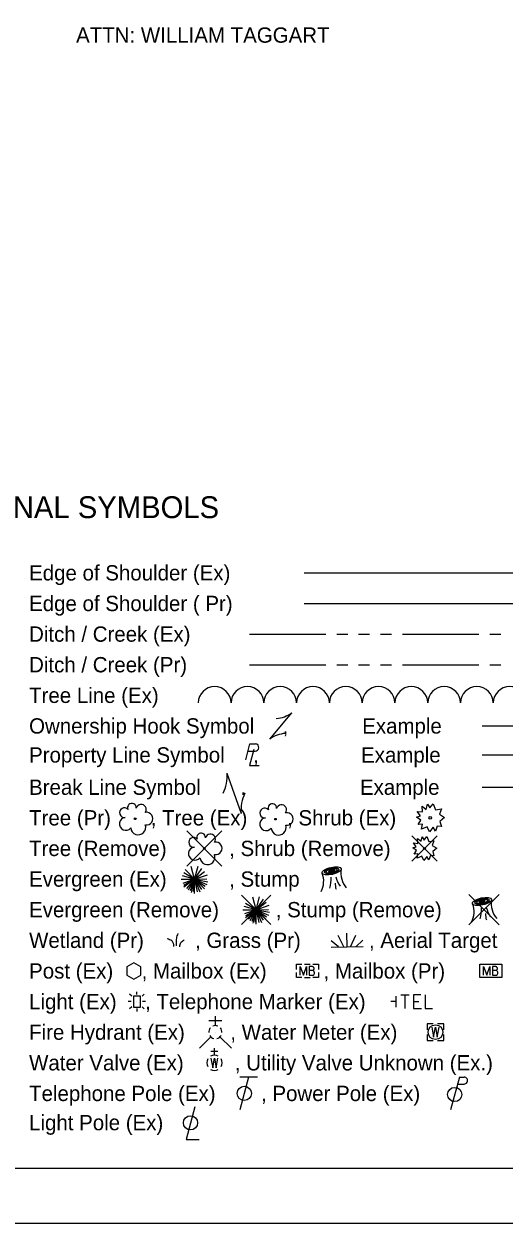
# Model space of a CAD drawing. Extents: x 0 to 34, y 0 to 22.
# Drawn here: x 8.12 to 12.52, y 0 to 10.96 of the extents above; entities that cross this region are included whole.
import ezdxf

# ---------------------------------------------------------------- set-up
doc = ezdxf.new("R2010")
doc.units = 0
for name, color, linetype in [('SH_Border', 7, 'Continuous'), ('SH_Cut_Line', 7, 'Continuous'), ('SH_Text', 7, 'Continuous')]:
    doc.layers.add(name, color=color, linetype=linetype)

msp = doc.modelspace()

# ---------------------------------------------------------------- linework, layer by layer
at = {"layer": 'SH_Border'}
msp.add_lwpolyline([(1.5, 21.5), (33.5, 21.5), (33.5, 0.5), (1.5, 0.5)], close=True, dxfattribs=at)
at = {"layer": 'SH_Cut_Line'}
msp.add_lwpolyline([(0, 0), (34, 0), (34, 22), (0, 22)], close=True, dxfattribs=at)
at = {"layer": 'SH_Text'}
for p, q in [((10.688, 5.945), (14.172, 5.945)), ((10.688, 5.665), (14.172, 5.665)), ((10.188, 5.385), (10.888, 5.385)), ((10.988, 5.385), (11.088, 5.385)), ((11.188, 5.385), (11.288, 5.385)), ((11.388, 5.385), (11.488, 5.385)), ((11.588, 5.385), (12.288, 5.385)), ((12.388, 5.385), (12.488, 5.385)), ((10.188, 5.105), (10.888, 5.105)), ((10.988, 5.105), (11.088, 5.105)), ((11.188, 5.105), (11.288, 5.105)), ((11.388, 5.105), (11.488, 5.105)), ((11.588, 5.105), (12.288, 5.105)), ((12.388, 5.105), (12.488, 5.105)), ((10.375, 4.425), (10.575, 4.665)), ((10.475, 4.545), (10.475, 4.545)), ((12.318, 4.545), (14.1, 4.545)), ((10.175, 4.314), (10.24, 4.314)), ((10.215, 4.283), (10.215, 4.283)), ((12.318, 4.28), (14.1, 4.28)), ((9.983, 4.113), (10.113, 3.745)), ((12.318, 3.985), (13.083, 3.985)), ((10.048, 3.929), (10.048, 3.929)), ((9.616, 3.585), (9.936, 3.264)), ((9.936, 3.585), (9.616, 3.264)), ((11.675, 3.541), (11.906, 3.309)), ((11.906, 3.541), (11.675, 3.309)), ((9.776, 3.425), (9.776, 3.425)), ((11.791, 3.425), (11.791, 3.425)), ((9.686, 3.144), (9.589, 3.202)), ((9.686, 3.144), (9.599, 3.232)), ((9.686, 3.144), (9.656, 3.26)), ((9.686, 3.144), (9.718, 3.262)), ((9.686, 3.144), (9.753, 3.242)), ((9.686, 3.144), (9.778, 3.215)), ((9.686, 3.144), (9.805, 3.185)), ((9.563, 3.144), (9.686, 3.144)), ((9.686, 3.144), (9.576, 3.174)), ((9.686, 3.144), (9.579, 3.105)), ((9.686, 3.144), (9.587, 3.087)), ((9.686, 3.144), (9.589, 3.07)), ((9.686, 3.144), (9.613, 3.058)), ((9.686, 3.144), (9.628, 3.044)), ((9.686, 3.144), (9.645, 3.036)), ((9.686, 3.144), (9.655, 3.023)), ((9.686, 3.144), (9.673, 3.03)), ((9.686, 3.144), (9.799, 3.147)), ((9.686, 3.013), (9.686, 3.144)), ((9.686, 3.144), (9.709, 3.029)), ((9.686, 3.144), (9.735, 3.028)), ((9.686, 3.144), (9.75, 3.05)), ((9.686, 3.144), (9.776, 3.056)), ((9.686, 3.144), (9.782, 3.081)), ((9.686, 3.144), (9.798, 3.096)), ((9.686, 3.144), (9.807, 3.12)), ((10.96, 3.145), (10.96, 3.145)), ((10.117, 2.998), (10.384, 2.731)), ((10.384, 2.998), (10.117, 2.731)), ((10.25, 2.865), (10.22, 2.98)), ((10.25, 2.865), (10.282, 2.982)), ((10.25, 2.865), (10.317, 2.962)), ((12.197, 3.004), (12.475, 2.726)), ((12.475, 3.004), (12.197, 2.726)), ((10.127, 2.865), (10.25, 2.865)), ((10.25, 2.865), (10.14, 2.894)), ((10.25, 2.865), (10.143, 2.826)), ((10.25, 2.865), (10.151, 2.808)), ((10.25, 2.865), (10.153, 2.922)), ((10.25, 2.865), (10.153, 2.79)), ((10.25, 2.865), (10.163, 2.952)), ((10.25, 2.865), (10.177, 2.778)), ((10.25, 2.865), (10.192, 2.764)), ((10.25, 2.865), (10.209, 2.756)), ((10.25, 2.865), (10.219, 2.743)), ((10.25, 2.865), (10.237, 2.75)), ((10.25, 2.865), (10.342, 2.935)), ((10.25, 2.865), (10.369, 2.905)), ((10.25, 2.865), (10.363, 2.867)), ((10.25, 2.734), (10.25, 2.865)), ((10.25, 2.865), (10.273, 2.749)), ((10.25, 2.865), (10.299, 2.748)), ((10.25, 2.865), (10.314, 2.77)), ((10.25, 2.865), (10.34, 2.777)), ((10.25, 2.865), (10.346, 2.801)), ((10.25, 2.865), (10.362, 2.816)), ((10.25, 2.865), (10.371, 2.841)), ((10.25, 2.865), (10.25, 2.865)), ((12.336, 2.865), (12.336, 2.865)), ((12.336, 2.865), (12.336, 2.865)), ((11.082, 2.525), (11.08, 2.65)), ((11.112, 2.525), (11.161, 2.633)), ((11.003, 2.524), (10.935, 2.581)), ((10.936, 2.522), (11.228, 2.527)), ((11.052, 2.524), (11, 2.63)), ((11.161, 2.526), (11.227, 2.585)), ((10.693, 2.366), (10.743, 2.366)), ((10.719, 2.305), (10.719, 2.305)), ((12.397, 2.305), (12.397, 2.305)), ((10.693, 2.244), (10.743, 2.244)), ((9.111, 2.073), (9.092, 2.092)), ((9.159, 2.089), (9.159, 2.115)), ((9.226, 2.092), (9.207, 2.073)), ((9.107, 2.025), (9.08, 2.025)), ((9.111, 1.976), (9.092, 1.958)), ((9.159, 2.025), (9.159, 2.025)), ((9.226, 1.958), (9.207, 1.976)), ((9.238, 2.025), (9.211, 2.025)), ((11.532, 2.025), (11.482, 2.025)), ((11.532, 1.975), (11.532, 2.075)), ((9.159, 1.961), (9.159, 1.934)), ((9.877, 1.805), (9.877, 1.891)), ((9.937, 1.848), (9.817, 1.848)), ((9.835, 1.702), (9.731, 1.598)), ((9.877, 1.745), (9.877, 1.745)), ((9.877, 1.745), (9.877, 1.745)), ((9.919, 1.702), (10.023, 1.598)), ((11.891, 1.745), (11.891, 1.745)), ((9.9, 1.567), (9.836, 1.567)), ((9.868, 1.535), (9.868, 1.598)), ((9.868, 1.465), (9.868, 1.465)), ((10.261, 1.335), (10.101, 1.335)), ((10.181, 1.335), (10.101, 1.035)), ((12.11, 1.335), (12.03, 1.035)), ((12.11, 1.335), (12.153, 1.335)), ((12.093, 1.271), (12.153, 1.271))]:
    msp.add_line(p, q, dxfattribs=at)
for points in [[(10.154, 4.234), (10.193, 4.382), (10.245, 4.382)], [(10.229, 4.331), (10.189, 4.183), (10.277, 4.183)], [(11.839, 3.795), (11.869, 3.832), (11.89, 3.779), (11.945, 3.788), (11.928, 3.738), (11.975, 3.708), (11.932, 3.671), (11.945, 3.626), (11.907, 3.629), (11.891, 3.583), (11.869, 3.618), (11.836, 3.577), (11.814, 3.621), (11.763, 3.6), (11.773, 3.647), (11.732, 3.643), (11.756, 3.682), (11.717, 3.711), (11.754, 3.724), (11.724, 3.764), (11.771, 3.759), (11.769, 3.81), (11.807, 3.782), (11.817, 3.831), (11.839, 3.795)], [(11.787, 3.502), (11.813, 3.533), (11.83, 3.488), (11.877, 3.496), (11.862, 3.453), (11.902, 3.427), (11.866, 3.396), (11.877, 3.357), (11.845, 3.36), (11.831, 3.321), (11.813, 3.351), (11.784, 3.316), (11.766, 3.354), (11.722, 3.336), (11.73, 3.376), (11.696, 3.372), (11.716, 3.406), (11.683, 3.43), (11.715, 3.441), (11.689, 3.475), (11.729, 3.47), (11.727, 3.515), (11.759, 3.49), (11.768, 3.532), (11.787, 3.502)], [(9.066, 2.267), (9.131, 2.23), (9.196, 2.267), (9.196, 2.342), (9.131, 2.38), (9.066, 2.342), (9.066, 2.267)], [(10.619, 2.317), (10.619, 2.366), (10.667, 2.366)], [(10.654, 2.265), (10.654, 2.345), (10.683, 2.265), (10.711, 2.345), (10.711, 2.265)], [(10.77, 2.308), (10.773, 2.311), (10.775, 2.313), (10.776, 2.315), (10.777, 2.316), (10.778, 2.319), (10.779, 2.321), (10.78, 2.325), (10.78, 2.327), (10.78, 2.33), (10.779, 2.333), (10.778, 2.336), (10.776, 2.339), (10.773, 2.342), (10.77, 2.343), (10.769, 2.343), (10.766, 2.345), (10.735, 2.345), (10.735, 2.265), (10.77, 2.265), (10.774, 2.267), (10.778, 2.27), (10.781, 2.275), (10.783, 2.281), (10.784, 2.287), (10.784, 2.291), (10.782, 2.294), (10.78, 2.3), (10.777, 2.304), (10.77, 2.308), (10.735, 2.308)], [(10.769, 2.366), (10.819, 2.366), (10.819, 2.317)], [(12.332, 2.265), (12.332, 2.345), (12.361, 2.265), (12.389, 2.345), (12.389, 2.265)], [(12.448, 2.308), (12.451, 2.311), (12.453, 2.313), (12.454, 2.315), (12.455, 2.316), (12.456, 2.319), (12.457, 2.321), (12.458, 2.325), (12.458, 2.327), (12.458, 2.33), (12.457, 2.333), (12.456, 2.336), (12.454, 2.339), (12.451, 2.342), (12.449, 2.343), (12.447, 2.343), (12.444, 2.345), (12.413, 2.345), (12.413, 2.265), (12.448, 2.265), (12.452, 2.267), (12.456, 2.27), (12.459, 2.275), (12.461, 2.281), (12.462, 2.287), (12.462, 2.291), (12.461, 2.294), (12.458, 2.3), (12.455, 2.304), (12.448, 2.308), (12.413, 2.308)], [(10.667, 2.244), (10.619, 2.244), (10.619, 2.292)], [(10.819, 2.292), (10.819, 2.244), (10.769, 2.244)], [(11.573, 2.087), (11.65, 2.087)], [(11.612, 2.087), (11.612, 1.962)], [(11.758, 2.087), (11.69, 2.087), (11.69, 1.962), (11.763, 1.962)], [(11.797, 2.087), (11.797, 1.962), (11.865, 1.962)], [(11.69, 2.025), (11.738, 2.025)], [(11.871, 1.82), (11.816, 1.82), (11.816, 1.765)], [(11.857, 1.79), (11.874, 1.7), (11.891, 1.79), (11.907, 1.7), (11.924, 1.79)], [(11.966, 1.765), (11.966, 1.82), (11.911, 1.82)], [(11.816, 1.725), (11.816, 1.67), (11.871, 1.67)], [(11.911, 1.67), (11.966, 1.67), (11.966, 1.725)], [(9.836, 1.506), (9.852, 1.42), (9.868, 1.506), (9.884, 1.42), (9.9, 1.506)], [(9.688, 1.063), (9.61, 0.764), (9.728, 0.764)]]:
    msp.add_lwpolyline(points, dxfattribs=at)
for points in [[(12.297, 2.366), (12.497, 2.366), (12.497, 2.244), (12.297, 2.244)], [(9.126, 1.975), (9.192, 1.975), (9.192, 2.075), (9.126, 2.075)]]:
    msp.add_lwpolyline(points, close=True, dxfattribs=at)
for centre, radius in [((9.143, 3.697), 0.0084), ((10.427, 3.693), 0.0072), ((11.843, 3.705), 0.0115), ((9.776, 3.425), 0.0072), ((11.79, 3.425), 0.00979), ((11.891, 1.745), 0.0675), ((10.141, 1.185), 0.065), ((12.067, 1.175), 0.065), ((9.649, 0.916), 0.065)]:
    msp.add_circle(centre, radius, dxfattribs=at)
for centre, radius, start, end in [((9.87, 4.755), 0.15, 0.0098, 179.9926), ((10.17, 4.755), 0.15, 0.0098, 179.9926), ((10.47, 4.755), 0.15, 0.0098, 179.9926), ((10.77, 4.755), 0.15, 0.0098, 179.9926), ((11.07, 4.755), 0.15, 0.0098, 179.9926), ((11.37, 4.755), 0.15, 0.0098, 179.9926), ((11.67, 4.755), 0.15, 0.0098, 179.9926), ((11.97, 4.755), 0.15, 0.0098, 179.9926), ((12.27, 4.755), 0.15, 0.0098, 179.9926), ((12.57, 4.755), 0.15, 0.0098, 179.9926), ((10.417, 4.88), 0.267, 273.6945, 306.337), ((10.533, 4.21), 0.267, 93.6945, 126.337), ((10.24, 4.348), 0.0345, 270.471, 81.3281), ((9.651, 4.081), 0.334, 332.9422, 5.5848), ((10.445, 3.777), 0.334, 152.9422, 185.5848), ((9.044, 3.752), 0.0441, 39.0625, 279.5412), ((9.113, 3.798), 0.0395, 354.0047, 205.9741), ((9.198, 3.781), 0.0466, 323.83, 165.0376), ((9.247, 3.698), 0.0574, 259.1453, 101.4596), ((10.328, 3.749), 0.0441, 39.0625, 279.5412), ((10.398, 3.794), 0.0395, 354.0047, 205.9741), ((10.482, 3.778), 0.0466, 323.83, 165.0376), ((10.531, 3.694), 0.0574, 259.1453, 101.4596), ((9.057, 3.65), 0.0592, 96.1722, 320.5737), ((9.171, 3.618), 0.0685, 184.9476, 19.4572), ((10.342, 3.647), 0.0592, 96.1722, 320.5737), ((10.456, 3.615), 0.0685, 184.9476, 19.4572), ((9.677, 3.481), 0.0441, 39.0625, 279.5412), ((9.746, 3.526), 0.0395, 354.0047, 205.9741), ((9.831, 3.51), 0.0466, 323.83, 165.0376), ((9.69, 3.378), 0.0592, 96.1722, 320.5737), ((9.88, 3.426), 0.0574, 259.1453, 101.4596), ((9.804, 3.346), 0.0685, 184.9476, 19.4572), ((10.668, 3.127), 0.2, 331.5338, 20.9269), ((11.24, 3.202), 0.215, 171.4106, 219.9194), ((10.684, 3.146), 0.253, 340.7938, 3.5481), ((11.155, 3.105), 0.182, 178.7926, 197.1224), ((11.285, 3.247), 0.316, 194.9653, 212.1216), ((12.044, 2.847), 0.2, 331.5338, 20.9269), ((12.06, 2.866), 0.253, 340.7938, 3.5481), ((12.661, 2.967), 0.316, 194.9653, 212.1216), ((12.616, 2.922), 0.215, 171.4106, 219.9194), ((12.531, 2.825), 0.182, 178.7926, 197.1224), ((9.877, 1.745), 0.06, 140.021, 184.0629), ((9.877, 1.745), 0.06, 68.1395, 112.038), ((9.877, 1.745), 0.06, 356.0165, 39.9889), ((9.877, 1.745), 0.06, 211.8788, 255.8479), ((9.877, 1.745), 0.06, 283.8239, 329.9097), ((9.868, 1.465), 0.07, 150.0184, 209.9816), ((9.868, 1.465), 0.07, 60.0184, 120.0157), ((9.868, 1.465), 0.07, 330.0184, 29.9816), ((9.868, 1.465), 0.07, 239.9843, 299.9816), ((12.153, 1.303), 0.0319, 268.8767, 91.1233)]:
    msp.add_arc(centre, radius, start, end, dxfattribs=at)
for centre, major_axis in [((10.941, 3.22), (0.0868, 0.0187)), ((10.941, 3.22), (0.0651, 0.0141)), ((10.941, 3.22), (0.0488, 0.0105)), ((10.941, 3.22), (0.0275, 0.0059)), ((10.941, 3.22), (0.0154, 0.0033)), ((12.317, 2.94), (0.0868, 0.0187)), ((12.317, 2.94), (0.0651, 0.0141)), ((12.317, 2.94), (0.0488, 0.0105)), ((12.317, 2.94), (0.0275, 0.0059)), ((12.317, 2.94), (0.0154, 0.0033))]:
    msp.add_ellipse(centre, major_axis=major_axis, ratio=0.36865, dxfattribs=at)
for points in [[(9.522, 2.533), (9.522, 2.581), (9.528, 2.625), (9.537, 2.646)], [(9.435, 2.6), (9.477, 2.583), (9.494, 2.529)], [(9.55, 2.526), (9.562, 2.564), (9.592, 2.588)]]:
    msp.add_spline(points, degree=3, dxfattribs=at)

# ---------------------------------------------------------------- texts
for s, height, p in [('ATTN: WILLIAM TAGGART', 0.14, (8.602, 10.792)), ('CONVENTIONAL SYMBOLS', 0.2, (6.433, 6.445)), ('Edge of Shoulder (Ex)', 0.14, (8.172, 5.875)), ('Edge of Shoulder ( Pr)', 0.14, (8.172, 5.595)), ('Ditch / Creek (Ex)', 0.14, (8.172, 5.315)), ('Ditch / Creek (Pr)', 0.14, (8.172, 5.035)), ('Tree Line (Ex)', 0.14, (8.172, 4.755)), ('Ownership Hook Symbol     ,             Example', 0.14, (8.172, 4.475)), ('Property Line Symbol     ,                  Example', 0.14, (8.172, 4.21)), ('Break Line Symbol       ,                    Example', 0.14, (8.172, 3.915)), ('Tree (Pr)       , Tree (Ex)       , Shrub (Ex)', 0.14, (8.172, 3.635)), ('Tree (Remove)           , Shrub (Remove)', 0.14, (8.172, 3.355)), ('Evergreen (Ex)           , Stump ', 0.14, (8.172, 3.075)), ('Evergreen (Remove)          , Stump (Remove)', 0.14, (8.172, 2.795)), ('Wetland (Pr)         , Grass (Pr)            , Aerial Target    ', 0.14, (8.172, 2.515)), ('Post (Ex)     , Mailbox (Ex)          , Mailbox (Pr)', 0.14, (8.172, 2.235)), ('Light (Ex)     , Telephone Marker (Ex)     ', 0.14, (8.172, 1.955)), ('Fire Hydrant (Ex)        , Water Meter (Ex)', 0.14, (8.172, 1.675)), ('Water Valve (Ex)         , Utility Valve Unknown (Ex.)', 0.14, (8.172, 1.395)), ('Telephone Pole (Ex)        , Power Pole (Ex)', 0.14, (8.172, 1.115)), ('Light Pole (Ex)     ', 0.14, (8.172, 0.848))]:
    msp.add_text(s, height=height, dxfattribs=at).set_placement(p)

doc.saveas('drawing.dxf')
